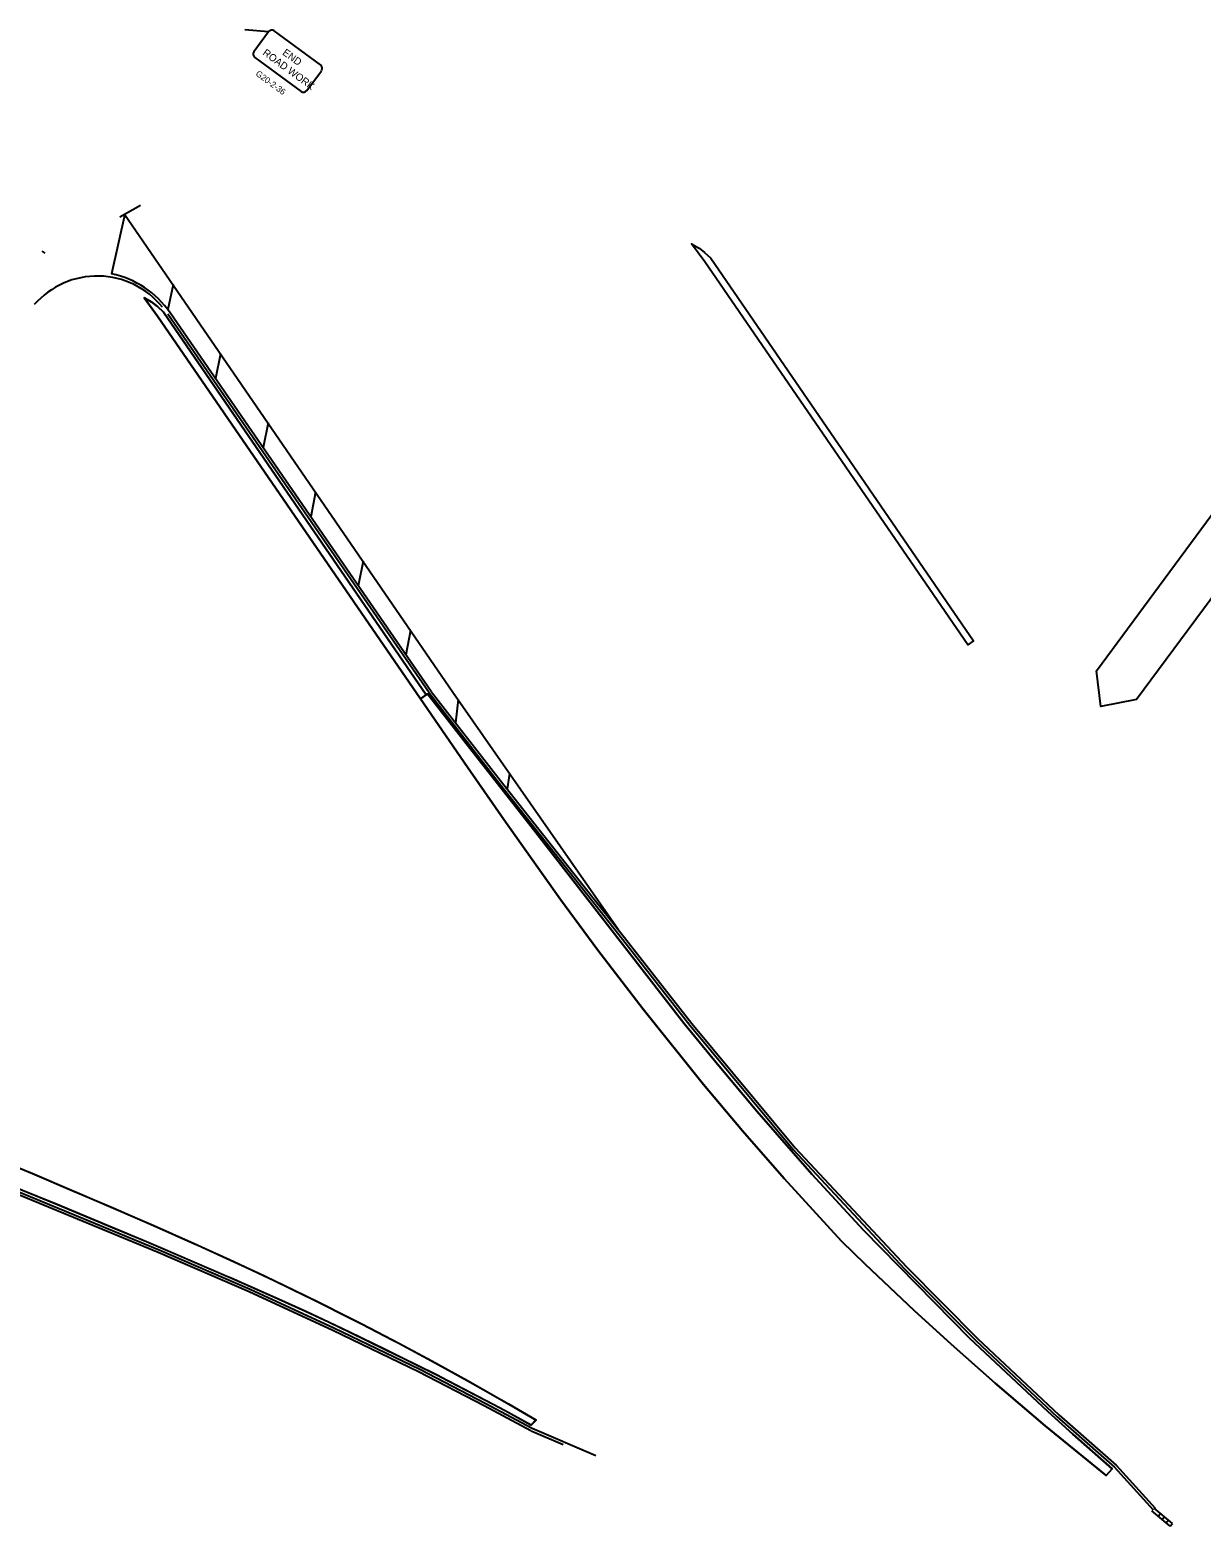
# Model space of a CAD drawing. Extents: x 1324973 to 1326617, y 459576 to 460945.
# Drawn here: x 1325311 to 1325981, y 459576 to 460432 of the extents above; entities that cross this region are included whole.
import ezdxf

# ---------------------------------------------------------------- set-up
doc = ezdxf.new("R2010")
doc.units = 0
for name, color, linetype in [('BR_P_Beam_Centerline', 7, 'Continuous'), ('BR_P_Rail_Object', 7, 'Continuous'), ('BR_P_Slab_Object', 7, 'Continuous'), ('BR_P_Sub_Foot_Object', 7, 'Continuous'), ('BR_X_Dia_Text', 7, 'Continuous'), ('BR_X_Slab_Object', 7, 'Continuous'), ('BR_X_Sub_Foot_Object', 7, 'Continuous'), ('BR_X_Sub_Object', 7, 'Continuous'), ('Default', 7, 'Continuous'), ('SC_Scratch17', 7, 'Continuous')]:
    doc.layers.add(name, color=color, linetype=linetype)

msp = doc.modelspace()

# ---------------------------------------------------------------- linework, layer by layer
at = {"layer": 'BR_P_Beam_Centerline'}
msp.add_arc((1325349.89, 460242.9), 48, 38.98638, 138.72944, dxfattribs=at)
at = {"layer": 'BR_P_Rail_Object'}
for p, q in [((1325365.56, 460326.28), (1325358.11, 460292.23)), ((1325393.24, 460285.99), (1325390.29, 460271.87)), ((1325420.4, 460246.45), (1325417.48, 460232.31)), ((1325447.58, 460206.89), (1325444.73, 460192.8)), ((1325474.76, 460167.33), (1325471.99, 460153.29)), ((1325501.94, 460127.77), (1325499.25, 460113.78)), ((1325529.12, 460088.2), (1325526.51, 460074.27)), ((1325556.34, 460048.66), (1325554.84, 460035.5)), ((1325585.83, 460006.43), (1325584.42, 459997.59))]:
    msp.add_line(p, q, dxfattribs=at)
at = {"layer": 'BR_P_Sub_Foot_Object'}
for p, q in [((1325365.5, 460326.37), (1325553.33, 460052.97)), ((1325540.97, 460053.32), (1325391.52, 460269.93)), ((1325540.97, 460053.32), (1325391.52, 460269.93)), ((1325540.92, 460053.39), (1325580.43, 460002.64)), ((1325553.33, 460052.98), (1325647.96, 459917.44)), ((1325580.43, 460002.64), (1325616.08, 459957.53)), ((1325616.08, 459957.53), (1325651.62, 459912.57)), ((1325651.62, 459912.57), (1325690.12, 459863.46)), ((1325690.12, 459863.46), (1325749.19, 459792.36)), ((1325749.19, 459792.36), (1325812.91, 459724.25)), ((1325298.82, 459768.19), (1325384.64, 459732.74)), ((1325298.82, 459768.19), (1325384.64, 459732.74)), ((1325384.64, 459732.74), (1325436.71, 459710.12)), ((1325384.64, 459732.74), (1325436.71, 459710.12)), ((1325812.91, 459724.25), (1325853.77, 459683.12)), ((1325436.71, 459710.12), (1325484.59, 459688.08)), ((1325436.71, 459710.12), (1325484.59, 459688.08)), ((1325484.59, 459688.08), (1325533.71, 459664.4)), ((1325484.59, 459688.08), (1325533.71, 459664.4)), ((1325853.77, 459683.12), (1325900.1, 459639.61)), ((1325533.71, 459664.4), (1325571.2, 459645.02)), ((1325533.71, 459664.4), (1325571.2, 459645.02)), ((1325571.2, 459645.02), (1325597.94, 459630.67)), ((1325571.2, 459645.02), (1325597.94, 459630.67)), ((1325900.1, 459639.61), (1325932.95, 459610.84)), ((1325598.08, 459630.59), (1325616.55, 459622.71)), ((1325932.95, 459610.84), (1325955.26, 459586.36))]:
    msp.add_line(p, q, dxfattribs=at)
msp.add_arc((1325346.77, 460239.06), 54.37, 34.60256, 77.95843, dxfattribs=at)
at = {"layer": 'BR_X_Dia_Text'}
for p, q in [((1325362.86, 460324.73), (1325374.69, 460331.53)), ((1325320.07, 460303.94), (1325318.44, 460305.1)), ((1325965.03, 459577.6), (1325954.56, 459586.26)), ((1325963.75, 459576.06), (1325953.29, 459584.72)), ((1325956.92, 459581.72), (1325958.19, 459583.26)), ((1325959.13, 459579.89), (1325960.41, 459581.43)), ((1325961.44, 459577.97), (1325962.72, 459579.51)), ((1325963.75, 459576.06), (1325965.03, 459577.6))]:
    msp.add_line(p, q, dxfattribs=at)
at = {"layer": 'BR_X_Slab_Object'}
for points in [[(1325447.87, 460430.55), (1325439.55, 460419.21)], [(1325477.6, 460411.64), (1325451.14, 460431.05)], [(1325440.05, 460415.93), (1325466.51, 460396.52)], [(1325469.78, 460397.02), (1325478.1, 460408.36)]]:
    msp.add_lwpolyline(points, dxfattribs=at)
for centre, start, end in [((1325449.76, 460429.16), 53.73007, 143.73007), ((1325441.44, 460417.82), 143.73007, 233.73007), ((1325476.21, 460409.75), 323.73007, 53.73007), ((1325467.89, 460398.41), 233.73007, 323.73007)]:
    msp.add_arc(centre, 2.34, start, end, dxfattribs=at)
at = {"layer": 'BR_X_Sub_Foot_Object'}
for points in [[(1326170.16, 460401.56), (1326195.32, 460411.62), (1326194.1, 460385.29), (1325944.49, 460048.83), (1325924.08, 460044.8), (1325921.65, 460065.23)], [(1325697.48, 460298.99), (1325689.81, 460309.35), (1325694.23, 460306.94), (1325697.41, 460304.43), (1325700.88, 460301.21), (1325851.21, 460082.31), (1325847.98, 460080.02)], [(1325384.34, 460268.05), (1325376.67, 460278.41), (1325381.09, 460276), (1325384.27, 460273.49), (1325387.74, 460270.27), (1325538.07, 460051.37), (1325534.84, 460049.08)], [(1325384.34, 460268.05), (1325376.67, 460278.41), (1325381.09, 460276), (1325384.27, 460273.49), (1325387.74, 460270.27), (1325538.07, 460051.37), (1325534.84, 460049.08)], [(1325534.84, 460049.08), (1325538.07, 460051.37), (1325387.74, 460270.27), (1325384.27, 460273.49), (1325381.09, 460276), (1325376.67, 460278.41), (1325384.34, 460268.05)], [(1325384.34, 460268.05), (1325376.67, 460278.41), (1325381.09, 460276), (1325384.27, 460273.49), (1325387.74, 460270.27), (1325538.07, 460051.37), (1325534.84, 460049.08)], [(1325534.84, 460049.08), (1325538.88, 460051.94), (1325559.6, 460025.23), (1325598.09, 459976.21), (1325685.58, 459863.71), (1325704.71, 459840.13), (1325727.23, 459813.33), (1325758.77, 459777.37), (1325788.38, 459745.19), (1325848.87, 459683.61), (1325893.73, 459641.58), (1325908.06, 459628.66), (1325930.6, 459608.85), (1325927.23, 459605.07), (1325892.34, 459633.46), (1325863.65, 459657.85), (1325838.5, 459680.03), (1325817.34, 459699.31), (1325789.2, 459725.86), (1325775.68, 459739), (1325742.91, 459774.84), (1325719, 459802.18), (1325696.75, 459828.58), (1325662.17, 459871.58), (1325636.34, 459905.41), (1325614.97, 459934.45), (1325582.46, 459980.13), (1325561.65, 460010.06)], [(1325534.84, 460049.08), (1325538.88, 460051.94), (1325559.6, 460025.23), (1325598.09, 459976.21), (1325685.58, 459863.71), (1325704.71, 459840.13), (1325727.23, 459813.33), (1325758.77, 459777.37), (1325788.38, 459745.19), (1325848.87, 459683.61), (1325893.73, 459641.58), (1325908.06, 459628.66), (1325930.6, 459608.85), (1325927.23, 459605.07), (1325892.34, 459633.46), (1325863.65, 459657.85), (1325838.5, 459680.03), (1325817.34, 459699.31), (1325789.2, 459725.86), (1325775.68, 459739), (1325742.91, 459774.84), (1325719, 459802.18), (1325696.75, 459828.58), (1325662.17, 459871.58), (1325636.34, 459905.41), (1325614.97, 459934.45), (1325582.46, 459980.13), (1325561.65, 460010.06)], [(1325561.65, 460010.06), (1325582.46, 459980.13), (1325614.97, 459934.45), (1325636.34, 459905.41), (1325662.17, 459871.58), (1325696.75, 459828.58), (1325719, 459802.18), (1325742.91, 459774.84), (1325775.68, 459739), (1325789.2, 459725.86), (1325817.34, 459699.31), (1325838.5, 459680.03), (1325863.65, 459657.85), (1325892.34, 459633.46), (1325927.23, 459605.07), (1325930.6, 459608.85), (1325908.06, 459628.66), (1325893.73, 459641.58), (1325848.87, 459683.61), (1325788.38, 459745.19), (1325758.77, 459777.37), (1325727.23, 459813.33), (1325704.71, 459840.13), (1325685.58, 459863.71), (1325598.09, 459976.21), (1325559.6, 460025.23), (1325538.88, 460051.94), (1325534.84, 460049.08)]]:
    msp.add_lwpolyline(points, close=True, dxfattribs=at)
for points in [[(1325303.61, 459781.59), (1325312.85, 459777.67), (1325335.91, 459767.87), (1325338.19, 459766.9), (1325359, 459757.98), (1325372.81, 459751.99), (1325382.07, 459747.95), (1325405.12, 459737.73), (1325407.39, 459736.71), (1325428.11, 459727.27), (1325441.84, 459720.87), (1325451.02, 459716.52), (1325468.91, 459707.87), (1325473.78, 459705.48), (1325495.76, 459694.46), (1325500.89, 459691.83), (1325518.84, 459682.51), (1325522.4, 459680.63), (1325541.14, 459670.59), (1325548.81, 459666.4), (1325563.26, 459658.38), (1325574.98, 459651.76), (1325585.22, 459645.89), (1325600.91, 459636.73), (1325598, 459633.78), (1325582.81, 459642.19), (1325576.33, 459645.65), (1325546.26, 459661.29), (1325544.96, 459661.95), (1325531.48, 459668.67), (1325514.57, 459676.99), (1325494.24, 459686.89), (1325482.52, 459692.49), (1325469.05, 459698.77), (1325453.4, 459705.86), (1325439.74, 459711.94), (1325426.09, 459717.93), (1325424.93, 459718.44), (1325386.01, 459735.21), (1325377.98, 459738.62), (1325358.42, 459746.74), (1325326.96, 459759.9), (1325294.37, 459773.19)], [(1325303.73, 459781.54), (1325312.97, 459777.62), (1325336.03, 459767.82), (1325338.31, 459766.85), (1325359.12, 459757.93), (1325372.93, 459751.95), (1325382.19, 459747.9), (1325405.24, 459737.68), (1325407.51, 459736.66), (1325428.23, 459727.22), (1325441.96, 459720.82), (1325451.13, 459716.47), (1325469.03, 459707.82), (1325473.9, 459705.43), (1325495.88, 459694.41), (1325501.01, 459691.79), (1325518.96, 459682.46), (1325522.52, 459680.59), (1325541.26, 459670.54), (1325548.93, 459666.35), (1325563.38, 459658.34), (1325575.1, 459651.72), (1325585.34, 459645.84), (1325601.03, 459636.68), (1325598.12, 459633.73), (1325582.93, 459642.15), (1325576.45, 459645.61), (1325546.38, 459661.24), (1325545.07, 459661.91), (1325531.6, 459668.62), (1325514.69, 459676.94), (1325494.36, 459686.84), (1325482.64, 459692.45), (1325469.17, 459698.73), (1325453.52, 459705.82), (1325439.86, 459711.89), (1325426.21, 459717.88), (1325425.05, 459718.39), (1325386.13, 459735.16), (1325378.1, 459738.57), (1325358.54, 459746.7), (1325327.08, 459759.85), (1325294.49, 459773.14)]]:
    msp.add_lwpolyline(points, dxfattribs=at)
at = {"layer": 'BR_X_Sub_Object'}
msp.add_line((1325447.87, 460430.55), (1325434.22, 460431.66), dxfattribs=at)
at = {"layer": 'Default'}
msp.add_lwpolyline([(1326170.16, 460401.56), (1326195.32, 460411.62), (1326194.1, 460385.29), (1325944.49, 460048.83), (1325924.08, 460044.8), (1325921.65, 460065.23)], close=True, dxfattribs=at)
at = {"layer": 'SC_Scratch17'}
for p, q in [((1325539.73, 460052.47), (1325390.28, 460269.08)), ((1325539.73, 460052.47), (1325579.25, 460001.71)), ((1325579.25, 460001.71), (1325614.91, 459956.6)), ((1325614.91, 459956.6), (1325650.44, 459911.64)), ((1325650.44, 459911.64), (1325688.96, 459862.52)), ((1325688.96, 459862.52), (1325748.06, 459791.37)), ((1325748.06, 459791.37), (1325811.83, 459723.21)), ((1325299.39, 459769.58), (1325385.23, 459734.12)), ((1325385.23, 459734.12), (1325437.32, 459711.49)), ((1325811.83, 459723.21), (1325852.72, 459682.04)), ((1325437.32, 459711.49), (1325485.23, 459689.44)), ((1325485.23, 459689.44), (1325534.38, 459665.74)), ((1325852.72, 459682.04), (1325899.09, 459638.5)), ((1325534.38, 459665.74), (1325571.9, 459646.34)), ((1325571.9, 459646.34), (1325598.64, 459631.99)), ((1325899.09, 459638.5), (1325931.96, 459609.72)), ((1325598.66, 459631.97), (1325635.19, 459616.39)), ((1325931.65, 459609.93), (1325954.09, 459585.3))]:
    msp.add_line(p, q, dxfattribs=at)

# ---------------------------------------------------------------- texts
at = {"layer": 'BR_P_Slab_Object'}
msp.add_text('G20-2-36', height=3.5, rotation=323.73007, dxfattribs=at).set_placement((1325440.14, 460405.94))
at = {"layer": 'BR_X_Slab_Object'}
for s, p in [('ROAD WORK', (1325444.14, 460417.78)), ('END', (1325455.47, 460417.86))]:
    msp.add_text(s, height=4.167, rotation=323.73007, dxfattribs=at).set_placement(p)

doc.saveas('drawing.dxf')
